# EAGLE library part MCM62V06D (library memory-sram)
MEMORY
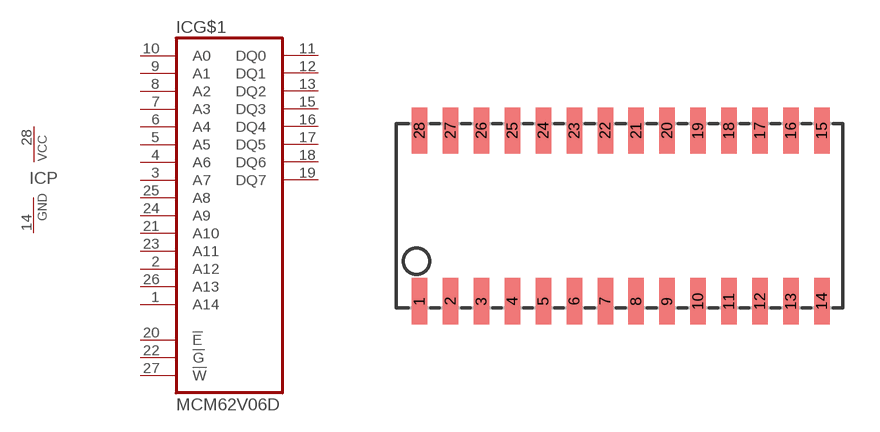
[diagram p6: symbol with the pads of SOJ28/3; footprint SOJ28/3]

Designator prefix IC; gates G$1=CM62V06D P=PWRN

## MCM62V06D  [SOJ28/3]
1  G$1:A14  in
2  G$1:A12  in
3  G$1:A7  in
4  G$1:A6  in
5  G$1:A5  in
6  G$1:A4  in
7  G$1:A3  in
8  G$1:A2  in
9  G$1:A1  in
10  G$1:A0  in
11  G$1:DQ0
12  G$1:DQ1
13  G$1:DQ2
14  P:GND  pwr
15  G$1:DQ3
16  G$1:DQ4
17  G$1:DQ5
18  G$1:DQ6
19  G$1:DQ7
20  G$1:!E  in
21  G$1:A10  in
22  G$1:!G  in
23  G$1:A11  in
24  G$1:A9  in
25  G$1:A8  in
26  G$1:A13  in
27  G$1:!W  in
28  P:VCC  pwr

## Footprint SOJ28/3 (pad centres in mm)
Small Outline J-Bend
smd 0.635 x 1.905: 1 -8.255,-3.505; 2 -6.985,-3.505; 3 -5.715,-3.505; 4 -4.445,-3.505; 5 -3.175,-3.505; 6 -1.905,-3.505; 7 -0.635,-3.505; 8 0.635,-3.505; 9 1.905,-3.505; 10 3.175,-3.505; 11 4.445,-3.505; 12 5.715,-3.505; 13 6.985,-3.505; 14 8.255,-3.505; 15 8.255,3.505; 16 6.985,3.505; 17 5.715,3.505; 18 4.445,3.505; 19 3.175,3.505; 20 1.905,3.505; 21 0.635,3.505; 22 -0.635,3.505; 23 -1.905,3.505; 24 -3.175,3.505; 25 -4.445,3.505; 26 -5.715,3.505; 27 -6.985,3.505; 28 -8.255,3.505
